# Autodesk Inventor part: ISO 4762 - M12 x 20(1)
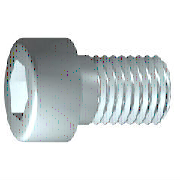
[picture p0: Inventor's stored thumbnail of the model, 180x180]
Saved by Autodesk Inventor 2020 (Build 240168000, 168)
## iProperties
IsCustomPart: 0
Created: 2019-01
Part Number: ISO 4762 - M12 x 20(1)
Material: Nerezová ocel 440C
Description: Šroub s válcovou hlavou s vnitřním šestihranem
Document SubType Name: Modeling
Standard: ISO 4762
Designer: doma
Standard Revision: Fourth edition 2004-03-01
Standards Organization: ISO
Language: cs-CZ
Size Designation: M12 x 20
Categories: <MemberInstance><Categories><Category DisplayName="Spojovací materiál" InternalName="e4da775c-781d-43d5-af7c-5136215cf5a6" Mnemonic="FSTN"><Category DisplayName
Density: 7.75 g/cm^3
Appearance: Pololeštěná
Mass: 36.0026 g
Surface Area: 21.1632 cm^2
Volume: 4.64549 cm^3
Author: doma
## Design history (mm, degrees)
sketch "Náčrt1"
  geometry: L1 (-2.667, 0)-(20, 0); L2 (20, 0)-(20, 6); L3 (20, 6)-(4.375, 6); L4 (4.375, 6)-(3.301, 6); L5 (3.301, 6)-(0, 6); L6 (0, 6)-(0, 9); L7 (0, 9)-(-12, 9); L8 (-12, 9)-(-12, 5.774); L9 (-12, 5.774)-(-6, 5.774); L10 (-6, 5.774)-(-2.667, 0); L11 (-18.4, 0)-(26.4, 0) reference; L12 (0, -1.8)-(0, 10.8) reference; L13 (4.375, 6)-(0, 6)
  constraints: 22 end point, 6 parallel, 2 collinear, 2 perpendicular, 1 horizontal, 1 point on line
  dimensions: "d1" = 15.625 distance from line of L3.end L2 (= GEL); "d2" = 1.07364 distance of L4.end L3.end (computed from GAL); "d3" = 12 distance between parallel lines of L8 L6 (= KOH); "d4" = 6 distance of L8.end L9.end (= INTI); "d5" = 60 deg angle of L10 L1; "d6" = 12 diameter of L3 L1 (= GD); "d7" = 12 diameter of L5 L1 (= BDM); "d8" = 11.54701 diameter of L9 L1 (= 1.1547 x SW); "d9" = 18 diameter of L7 L1 (= KOD); "d26" = 20 distance between parallel lines of L12 L2 (= NLG)
revolve "Těleso" sketch "Náčrt1" stored, may be unused: angle "d10" = 90 deg
sketch "Náčrt2"
  geometry: L1 (0, -12.6)-(0, 12.6) reference; L2 (-12.6, 0)-(12.6, 0) reference; L3 (5.774, 0)-(2.887, -5); L4 (2.887, -5)-(-2.887, -5); L5 (-2.887, -5)-(-5.774, 0); L6 (-5.774, 0)-(-2.887, 5); L7 (-2.887, 5)-(2.887, 5); L8 (2.887, 5)-(5.774, 0); 2 further points
  constraints: 12 end point, 1 coincident, 1 horizontal alignment, 1 point on line, 12 other
extrude "Drážka" join sketch "Náčrt2" stored distance "d11" = 10; taper "d12" = 0 deg
workplane "Work Plane1"
fillet "Fillet2" dims "d30" = 0.1 (= R)
body "Solid1"
fillet "Zaoblení1" dims "d17" = 1.2 (= RR)
feature "Závit" dims "d13" = 15.625 (= GEL), "d14" = 0
chamfer "Zkosení1" distance "d15" = 1.07354 (= -0.5 x SPD + 0.5 x GD); stored, may be unused: second distance "d16" = 1.07354 (= GUL), angle "d27" = 45 deg
other parameters: "GD" = 12 [user parameter; used in 2 equation terms], "NLG" = 20 [user parameter; used in 1 equation term], "GEL" = 15.625 [user parameter; used in 2 equation terms], "KOD" = 18 [user parameter; used in 1 equation term], "KOH" = 12 [user parameter; used in 1 equation term], "INTI" = 6 [user parameter; used in 1 equation term], "GAL" = 1.07354 (= 0.61345 x PTC) [user parameter; used in 1 equation term], "GUL" = 1.07354 (= 0.61345 x PTC) [user parameter; used in 1 equation term], "BDM" = 12 (= NND) [user parameter; used in 1 equation term], "RR" = 1.2 [user parameter; used in 1 equation term], "SPD" = 9.85293 (= NND - 1.2269 x PTC) [user parameter; used in 1 equation term], "d19" = 0, "d28" = 0, "d29" = 0, "R" = 0.1 [user parameter; used in 1 equation term], "TOA" = 30 deg [user parameter], "GD1" = 9.85293 (= THREADDIA - 1.2269 x PTC) [user parameter], "THREADDIA" = 12 [user parameter; used in 1 equation term], "FAWI" = 45 deg [user parameter], "TPU" = 5.71429 (computed from PTC) [user parameter], "PTC" = 1.75 [user parameter; used in 5 equation terms], "NND" = 12 [user parameter; used in 2 equation terms], "E0" = 11.55 (= 1.155 x SW) [user parameter]
